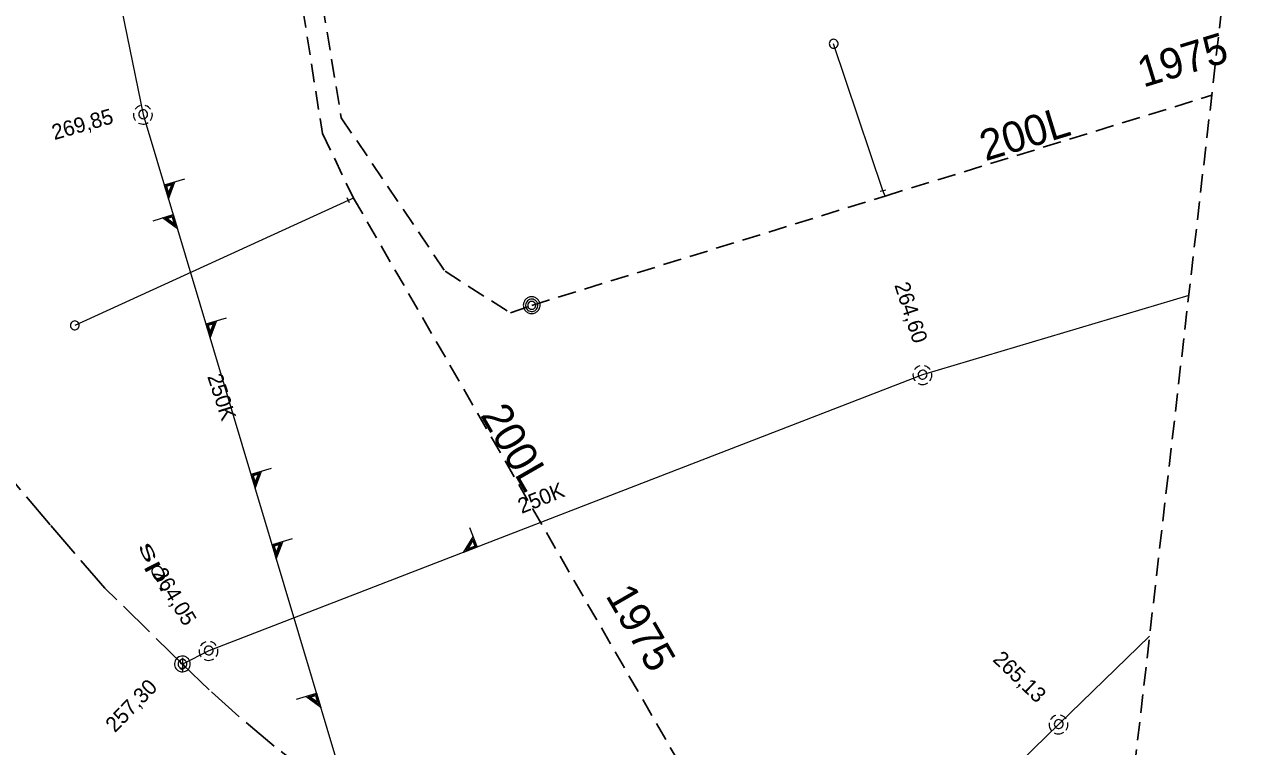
# Model space of a CAD drawing. Extents: x -743212 to -743020, y -1051380 to -1051228.
# Drawn here: x -743084.5 to -743020, y -1051298.4 to -1051260.7 of the extents above; entities that cross this region are included whole.
import ezdxf

# ---------------------------------------------------------------- set-up
doc = ezdxf.new("R2010")
doc.units = 0
doc.header["$LTSCALE"] = 0.32
doc.linetypes.add('LONG_DASHED', pattern=[7.5, 6, -1.5])
doc.linetypes.add('MEDIUM_DASHED', pattern=[4.5, 3, -1.5])
for name, color, linetype, lineweight in [('1', 7, 'MEDIUM_DASHED', 25), ('18', 7, 'Continuous', 13), ('20', 7, 'Continuous', 13), ('8', 7, 'Continuous', 13)]:
    doc.layers.add(name, color=color, linetype=linetype, lineweight=lineweight)

msp = doc.modelspace()

# ---------------------------------------------------------------- linework, layer by layer
at = {"layer": '1'}
msp.add_lwpolyline([(-743194.153, -1051227.724), (-743020.025, -1051242.759), (-743020.023, -1051242.759), (-743020.021, -1051242.76), (-743020.02, -1051242.761), (-743020.018, -1051242.762), (-743020.017, -1051242.764), (-743020.016, -1051242.766), (-743020.016, -1051242.768), (-743020.016, -1051242.77), (-743035.817, -1051380.315), (-743035.817, -1051380.317), (-743035.818, -1051380.318), (-743035.819, -1051380.32), (-743035.82, -1051380.321), (-743035.822, -1051380.322), (-743035.824, -1051380.323), (-743035.826, -1051380.323), (-743035.828, -1051380.323), (-743211.786, -1051358.847)], dxfattribs=at)
at = {"layer": '18'}
msp.add_line((-743076.25, -1051293.783), (-743076.25, -1051294.471), dxfattribs=at)
for points in [[(-743078.453, -1051264.936), (-743078.524, -1051264.964), (-743078.591, -1051265.003), (-743078.651, -1051265.051), (-743078.702, -1051265.108), (-743078.726, -1051265.142)], [(-743077.912, -1051265.119), (-743077.962, -1051265.061), (-743078.02, -1051265.011), (-743078.085, -1051264.97), (-743078.156, -1051264.941), (-743078.205, -1051264.927)], [(-743078.798, -1051265.328), (-743078.804, -1051265.405), (-743078.799, -1051265.482), (-743078.782, -1051265.557), (-743078.753, -1051265.628), (-743078.713, -1051265.694), (-743078.697, -1051265.716)], [(-743077.917, -1051265.705), (-743077.876, -1051265.64), (-743077.845, -1051265.57), (-743077.826, -1051265.495), (-743077.818, -1051265.419), (-743077.823, -1051265.342), (-743077.829, -1051265.307)], [(-743078.54, -1051265.845), (-743078.47, -1051265.876), (-743078.395, -1051265.895), (-743078.319, -1051265.902), (-743078.242, -1051265.897), (-743078.167, -1051265.88), (-743078.095, -1051265.852), (-743078.035, -1051265.817)], [(-743076.148, -1051268.771), (-743077.198, -1051269.085), (-743076.977, -1051269.824), (-743076.644, -1051268.919)], [(-743076.742, -1051269.002), (-743077.141, -1051269.121), (-743076.979, -1051269.663), (-743076.741, -1051269.002)], [(-743076.809, -1051269.071), (-743077.088, -1051269.155), (-743076.982, -1051269.51), (-743076.81, -1051269.07)], [(-743077.782, -1051270.946), (-743076.732, -1051270.631), (-743076.511, -1051271.369), (-743077.286, -1051270.797)], [(-743077.158, -1051270.811), (-743076.76, -1051270.692), (-743076.597, -1051271.234), (-743077.159, -1051270.812)], [(-743077.064, -1051270.832), (-743076.786, -1051270.749), (-743076.679, -1051271.105), (-743077.065, -1051270.831)], [(-743073.972, -1051276.038), (-743075.022, -1051276.352), (-743074.801, -1051277.091), (-743074.468, -1051276.186)], [(-743074.566, -1051276.269), (-743074.965, -1051276.388), (-743074.803, -1051276.93), (-743074.565, -1051276.269)], [(-743074.633, -1051276.338), (-743074.912, -1051276.422), (-743074.806, -1051276.777), (-743074.634, -1051276.337)], [(-743038.097, -1051278.928), (-743038.103, -1051279.005), (-743038.098, -1051279.082), (-743038.081, -1051279.157), (-743038.052, -1051279.228), (-743038.012, -1051279.294), (-743037.996, -1051279.316)], [(-743037.752, -1051278.536), (-743037.823, -1051278.564), (-743037.89, -1051278.603), (-743037.95, -1051278.651), (-743038.001, -1051278.708), (-743038.025, -1051278.742)], [(-743037.211, -1051278.719), (-743037.261, -1051278.661), (-743037.319, -1051278.611), (-743037.384, -1051278.57), (-743037.455, -1051278.541), (-743037.504, -1051278.527)], [(-743037.216, -1051279.305), (-743037.175, -1051279.24), (-743037.144, -1051279.17), (-743037.125, -1051279.095), (-743037.117, -1051279.019), (-743037.122, -1051278.942), (-743037.128, -1051278.907)], [(-743037.839, -1051279.445), (-743037.769, -1051279.476), (-743037.694, -1051279.495), (-743037.618, -1051279.502), (-743037.541, -1051279.497), (-743037.466, -1051279.48), (-743037.394, -1051279.452), (-743037.334, -1051279.417)], [(-743071.622, -1051283.886), (-743072.672, -1051284.2), (-743072.451, -1051284.939), (-743072.118, -1051284.034)], [(-743072.216, -1051284.117), (-743072.615, -1051284.236), (-743072.453, -1051284.778), (-743072.215, -1051284.117)], [(-743072.283, -1051284.186), (-743072.562, -1051284.27), (-743072.456, -1051284.625), (-743072.284, -1051284.185)], [(-743061.258, -1051286.97), (-743060.863, -1051287.992), (-743061.582, -1051288.27), (-743061.072, -1051287.453)], [(-743070.519, -1051287.568), (-743071.569, -1051287.882), (-743071.348, -1051288.621), (-743071.015, -1051287.716)], [(-743071.113, -1051287.799), (-743071.512, -1051287.918), (-743071.35, -1051288.46), (-743071.112, -1051287.799)], [(-743071.18, -1051287.868), (-743071.459, -1051287.952), (-743071.353, -1051288.307), (-743071.181, -1051287.867)], [(-743061.076, -1051287.581), (-743060.926, -1051287.969), (-743061.454, -1051288.173), (-743061.076, -1051287.58)], [(-743061.089, -1051287.676), (-743060.984, -1051287.948), (-743061.331, -1051288.082), (-743061.088, -1051287.676)], [(-743075.377, -1051293.338), (-743075.382, -1051293.415), (-743075.377, -1051293.492), (-743075.36, -1051293.567), (-743075.331, -1051293.638), (-743075.291, -1051293.704), (-743075.276, -1051293.726)], [(-743075.032, -1051292.946), (-743075.103, -1051292.974), (-743075.169, -1051293.013), (-743075.23, -1051293.061), (-743075.281, -1051293.118), (-743075.304, -1051293.152)], [(-743074.49, -1051293.129), (-743074.541, -1051293.071), (-743074.598, -1051293.021), (-743074.664, -1051292.98), (-743074.735, -1051292.951), (-743074.784, -1051292.937)], [(-743074.495, -1051293.715), (-743074.455, -1051293.65), (-743074.424, -1051293.58), (-743074.404, -1051293.505), (-743074.397, -1051293.429), (-743074.402, -1051293.352), (-743074.407, -1051293.317)], [(-743076.126, -1051293.93), (-743076.146, -1051293.897), (-743076.175, -1051293.871), (-743076.211, -1051293.854), (-743076.251, -1051293.85), (-743076.289, -1051293.857), (-743076.324, -1051293.876), (-743076.352, -1051293.904), (-743076.37, -1051293.939), (-743076.376, -1051293.978), (-743076.371, -1051294.017), (-743076.354, -1051294.053), (-743076.327, -1051294.082), (-743076.293, -1051294.101), (-743076.255, -1051294.11)], [(-743075.119, -1051293.855), (-743075.049, -1051293.886), (-743074.973, -1051293.905), (-743074.897, -1051293.912), (-743074.821, -1051293.907), (-743074.745, -1051293.89), (-743074.674, -1051293.862), (-743074.614, -1051293.827)], [(-743076.385, -1051294.297), (-743076.363, -1051294.33), (-743076.332, -1051294.355), (-743076.295, -1051294.369), (-743076.256, -1051294.372), (-743076.217, -1051294.363), (-743076.183, -1051294.343), (-743076.157, -1051294.313), (-743076.14, -1051294.277), (-743076.135, -1051294.238), (-743076.142, -1051294.199), (-743076.16, -1051294.164), (-743076.188, -1051294.136), (-743076.223, -1051294.117), (-743076.255, -1051294.11)], [(-743070.296, -1051295.944), (-743069.246, -1051295.629), (-743069.025, -1051296.367), (-743069.8, -1051295.795)], [(-743069.672, -1051295.809), (-743069.274, -1051295.69), (-743069.111, -1051296.232), (-743069.673, -1051295.81)], [(-743069.578, -1051295.83), (-743069.3, -1051295.747), (-743069.193, -1051296.103), (-743069.579, -1051295.829)], [(-743030.988, -1051297.181), (-743030.994, -1051297.258), (-743030.989, -1051297.335), (-743030.972, -1051297.41), (-743030.943, -1051297.481), (-743030.902, -1051297.547), (-743030.887, -1051297.569)], [(-743030.643, -1051296.789), (-743030.714, -1051296.817), (-743030.781, -1051296.856), (-743030.841, -1051296.904), (-743030.892, -1051296.961), (-743030.916, -1051296.995)], [(-743030.102, -1051296.972), (-743030.152, -1051296.914), (-743030.21, -1051296.864), (-743030.275, -1051296.823), (-743030.346, -1051296.794), (-743030.395, -1051296.78)], [(-743030.107, -1051297.558), (-743030.066, -1051297.493), (-743030.035, -1051297.423), (-743030.016, -1051297.348), (-743030.008, -1051297.272), (-743030.013, -1051297.195), (-743030.019, -1051297.16)], [(-743030.73, -1051297.698), (-743030.66, -1051297.729), (-743030.585, -1051297.748), (-743030.509, -1051297.755), (-743030.432, -1051297.75), (-743030.357, -1051297.733), (-743030.285, -1051297.705), (-743030.225, -1051297.67)]]:
    msp.add_lwpolyline(points, dxfattribs=at)
for points in [[(-743078.069, -1051265.388), (-743078.075, -1051265.336), (-743078.093, -1051265.286), (-743078.121, -1051265.242), (-743078.159, -1051265.205), (-743078.204, -1051265.178), (-743078.254, -1051265.162), (-743078.306, -1051265.157), (-743078.358, -1051265.164), (-743078.407, -1051265.183), (-743078.451, -1051265.213), (-743078.486, -1051265.252), (-743078.512, -1051265.297), (-743078.527, -1051265.348), (-743078.53, -1051265.4), (-743078.522, -1051265.452), (-743078.501, -1051265.5), (-743078.471, -1051265.543), (-743078.431, -1051265.578), (-743078.385, -1051265.602), (-743078.334, -1051265.616), (-743078.282, -1051265.618), (-743078.23, -1051265.608), (-743078.182, -1051265.586), (-743078.14, -1051265.554), (-743078.107, -1051265.514), (-743078.083, -1051265.467), (-743078.071, -1051265.416)], [(-743037.368, -1051278.988), (-743037.374, -1051278.936), (-743037.392, -1051278.886), (-743037.42, -1051278.842), (-743037.458, -1051278.805), (-743037.503, -1051278.778), (-743037.553, -1051278.762), (-743037.605, -1051278.757), (-743037.657, -1051278.764), (-743037.706, -1051278.783), (-743037.75, -1051278.813), (-743037.785, -1051278.852), (-743037.811, -1051278.897), (-743037.826, -1051278.948), (-743037.829, -1051279), (-743037.821, -1051279.052), (-743037.8, -1051279.1), (-743037.77, -1051279.143), (-743037.73, -1051279.178), (-743037.684, -1051279.202), (-743037.633, -1051279.216), (-743037.581, -1051279.218), (-743037.529, -1051279.208), (-743037.481, -1051279.186), (-743037.439, -1051279.154), (-743037.406, -1051279.114), (-743037.382, -1051279.067), (-743037.37, -1051279.016)], [(-743074.647, -1051293.398), (-743074.654, -1051293.346), (-743074.671, -1051293.296), (-743074.7, -1051293.252), (-743074.738, -1051293.215), (-743074.782, -1051293.188), (-743074.833, -1051293.172), (-743074.885, -1051293.167), (-743074.936, -1051293.174), (-743074.985, -1051293.193), (-743075.029, -1051293.223), (-743075.065, -1051293.262), (-743075.091, -1051293.307), (-743075.105, -1051293.358), (-743075.108, -1051293.41), (-743075.1, -1051293.462), (-743075.08, -1051293.51), (-743075.049, -1051293.553), (-743075.01, -1051293.588), (-743074.963, -1051293.612), (-743074.913, -1051293.626), (-743074.86, -1051293.628), (-743074.809, -1051293.618), (-743074.761, -1051293.596), (-743074.718, -1051293.564), (-743074.686, -1051293.524), (-743074.662, -1051293.477), (-743074.649, -1051293.426)], [(-743075.84, -1051294.1), (-743075.846, -1051294.03), (-743075.864, -1051293.963), (-743075.893, -1051293.899), (-743075.933, -1051293.841), (-743075.982, -1051293.79), (-743076.038, -1051293.749), (-743076.101, -1051293.717), (-743076.168, -1051293.697), (-743076.238, -1051293.689), (-743076.308, -1051293.692), (-743076.377, -1051293.708), (-743076.442, -1051293.735), (-743076.501, -1051293.772), (-743076.553, -1051293.819), (-743076.597, -1051293.875), (-743076.63, -1051293.936), (-743076.652, -1051294.003), (-743076.663, -1051294.072), (-743076.662, -1051294.143), (-743076.649, -1051294.212), (-743076.624, -1051294.277), (-743076.588, -1051294.338), (-743076.543, -1051294.392), (-743076.489, -1051294.437), (-743076.429, -1051294.472), (-743076.363, -1051294.497), (-743076.294, -1051294.51), (-743076.224, -1051294.511), (-743076.154, -1051294.5), (-743076.088, -1051294.478), (-743076.026, -1051294.445), (-743075.971, -1051294.401), (-743075.924, -1051294.349), (-743075.886, -1051294.29), (-743075.86, -1051294.225), (-743075.844, -1051294.156)], [(-743076.019, -1051294.099), (-743076.025, -1051294.047), (-743076.043, -1051293.997), (-743076.071, -1051293.953), (-743076.109, -1051293.916), (-743076.154, -1051293.889), (-743076.204, -1051293.873), (-743076.256, -1051293.868), (-743076.308, -1051293.875), (-743076.357, -1051293.894), (-743076.401, -1051293.924), (-743076.436, -1051293.963), (-743076.462, -1051294.008), (-743076.477, -1051294.059), (-743076.48, -1051294.111), (-743076.472, -1051294.163), (-743076.451, -1051294.211), (-743076.421, -1051294.254), (-743076.381, -1051294.289), (-743076.335, -1051294.313), (-743076.284, -1051294.327), (-743076.232, -1051294.329), (-743076.18, -1051294.319), (-743076.132, -1051294.297), (-743076.09, -1051294.265), (-743076.057, -1051294.225), (-743076.033, -1051294.178), (-743076.021, -1051294.127)], [(-743030.259, -1051297.241), (-743030.265, -1051297.189), (-743030.282, -1051297.139), (-743030.311, -1051297.095), (-743030.349, -1051297.058), (-743030.394, -1051297.031), (-743030.444, -1051297.015), (-743030.496, -1051297.01), (-743030.548, -1051297.017), (-743030.597, -1051297.036), (-743030.641, -1051297.066), (-743030.676, -1051297.105), (-743030.702, -1051297.15), (-743030.717, -1051297.201), (-743030.72, -1051297.253), (-743030.712, -1051297.305), (-743030.691, -1051297.353), (-743030.661, -1051297.396), (-743030.621, -1051297.431), (-743030.575, -1051297.455), (-743030.524, -1051297.469), (-743030.472, -1051297.471), (-743030.42, -1051297.461), (-743030.372, -1051297.439), (-743030.33, -1051297.407), (-743030.297, -1051297.367), (-743030.273, -1051297.32), (-743030.261, -1051297.269)]]:
    msp.add_lwpolyline(points, close=True, dxfattribs=at)
at = {"layer": '20'}
for p, q in [((-743084.112, -1051237.225), (-743078.3, -1051265.399)), ((-743084.112, -1051237.225), (-743078.3, -1051265.399)), ((-743078.3, -1051265.399), (-743067.1, -1051302.8)), ((-743078.3, -1051265.399), (-743067.1, -1051302.8)), ((-743023.701, -1051274.85), (-743037.599, -1051278.999)), ((-743023.701, -1051274.85), (-743037.599, -1051278.999)), ((-743037.599, -1051278.999), (-743074.879, -1051293.409)), ((-743037.599, -1051278.999), (-743074.879, -1051293.409)), ((-743025.745, -1051292.642), (-743030.49, -1051297.252)), ((-743025.745, -1051292.642), (-743030.49, -1051297.252)), ((-743074.879, -1051293.409), (-743076.25, -1051294.11)), ((-743074.879, -1051293.409), (-743076.25, -1051294.11)), ((-743030.49, -1051297.252), (-743053.699, -1051319.8)), ((-743030.49, -1051297.252), (-743053.699, -1051319.8))]:
    msp.add_line(p, q, dxfattribs=at)
at = {"layer": '20', "linetype": 'LONG_DASHED', "lineweight": 25}
for points in [[(-743076.25, -1051294.11), (-743080.298, -1051290.141), (-743083.155, -1051286.838), (-743088, -1051281.159)], [(-743076.25, -1051294.11), (-743080.298, -1051290.141), (-743083.155, -1051286.838), (-743088, -1051281.159)], [(-743069.586, -1051299.847), (-743071.454, -1051298.396), (-743073.302, -1051296.848), (-743074.85, -1051295.453), (-743076.25, -1051294.11)], [(-743069.586, -1051299.847), (-743071.454, -1051298.396), (-743073.302, -1051296.848), (-743074.85, -1051295.453), (-743076.25, -1051294.11)]]:
    msp.add_lwpolyline(points, dxfattribs=at)
at = {"layer": '8'}
for p, q in [((-743039.67, -1051269.37), (-743042.247, -1051261.713)), ((-743039.81, -1051269.407), (-743039.516, -1051269.329)), ((-743039.559, -1051269.659), (-743039.67, -1051269.37)), ((-743067.59, -1051269.889), (-743081.866, -1051276.423)), ((-743067.528, -1051270.021), (-743067.654, -1051269.744)), ((-743067.317, -1051269.764), (-743067.59, -1051269.889))]:
    msp.add_line(p, q, dxfattribs=at)
at = {"layer": '8', "linetype": 'MEDIUM_DASHED', "lineweight": 25}
for points in [[(-743072.836, -1051238.199), (-743072.636, -1051242.843), (-743068.943, -1051266.389), (-743067.317, -1051269.764), (-743041.789, -1051314.04)], [(-743071.973, -1051238.273), (-743071.77, -1051242.625), (-743067.953, -1051265.57), (-743062.537, -1051273.588), (-743059.127, -1051275.767), (-743058.006, -1051275.37)], [(-743058.006, -1051275.37), (-743039.559, -1051269.659), (-743022.5, -1051264.397)]]:
    msp.add_lwpolyline(points, dxfattribs=at)
at = {"layer": '8'}
for points in [[(-743042.023, -1051261.772), (-743042.013, -1051261.721), (-743042.015, -1051261.668), (-743042.029, -1051261.618), (-743042.054, -1051261.571), (-743042.088, -1051261.531), (-743042.131, -1051261.501), (-743042.179, -1051261.481), (-743042.231, -1051261.471), (-743042.283, -1051261.475), (-743042.334, -1051261.49), (-743042.379, -1051261.517), (-743042.418, -1051261.552), (-743042.448, -1051261.596), (-743042.466, -1051261.644), (-743042.474, -1051261.696), (-743042.469, -1051261.748), (-743042.453, -1051261.798), (-743042.426, -1051261.844), (-743042.389, -1051261.881), (-743042.345, -1051261.91), (-743042.296, -1051261.927), (-743042.243, -1051261.933), (-743042.191, -1051261.927), (-743042.141, -1051261.909), (-743042.098, -1051261.881), (-743042.06, -1051261.843), (-743042.034, -1051261.798)], [(-743057.689, -1051275.367), (-743057.695, -1051275.306), (-743057.713, -1051275.246), (-743057.742, -1051275.191), (-743057.781, -1051275.143), (-743057.828, -1051275.103), (-743057.882, -1051275.073), (-743057.941, -1051275.053), (-743058.003, -1051275.046), (-743058.065, -1051275.05), (-743058.125, -1051275.066), (-743058.18, -1051275.094), (-743058.23, -1051275.131), (-743058.271, -1051275.178), (-743058.303, -1051275.231), (-743058.323, -1051275.29), (-743058.333, -1051275.351), (-743058.33, -1051275.413), (-743058.315, -1051275.473), (-743058.289, -1051275.53), (-743058.253, -1051275.58), (-743058.207, -1051275.623), (-743058.155, -1051275.655), (-743058.097, -1051275.678), (-743058.036, -1051275.688), (-743057.974, -1051275.687), (-743057.913, -1051275.674), (-743057.856, -1051275.649), (-743057.805, -1051275.614), (-743057.761, -1051275.57), (-743057.727, -1051275.518), (-743057.703, -1051275.461), (-743057.691, -1051275.4)], [(-743057.803, -1051275.367), (-743057.809, -1051275.318), (-743057.826, -1051275.271), (-743057.854, -1051275.23), (-743057.892, -1051275.197), (-743057.936, -1051275.173), (-743057.984, -1051275.161), (-743058.034, -1051275.16), (-743058.082, -1051275.172), (-743058.127, -1051275.194), (-743058.165, -1051275.227), (-743058.194, -1051275.267), (-743058.213, -1051275.314), (-743058.22, -1051275.363), (-743058.215, -1051275.413), (-743058.198, -1051275.46), (-743058.171, -1051275.502), (-743058.134, -1051275.536), (-743058.091, -1051275.56), (-743058.043, -1051275.574), (-743057.993, -1051275.575), (-743057.944, -1051275.565), (-743057.899, -1051275.543), (-743057.86, -1051275.511), (-743057.83, -1051275.472), (-743057.811, -1051275.426), (-743057.803, -1051275.376)], [(-743081.66, -1051276.317), (-743081.687, -1051276.272), (-743081.724, -1051276.234), (-743081.768, -1051276.206), (-743081.818, -1051276.188), (-743081.87, -1051276.182), (-743081.922, -1051276.188), (-743081.971, -1051276.205), (-743082.016, -1051276.233), (-743082.052, -1051276.271), (-743082.08, -1051276.317), (-743082.096, -1051276.367), (-743082.101, -1051276.418), (-743082.093, -1051276.471), (-743082.074, -1051276.52), (-743082.045, -1051276.564), (-743082.006, -1051276.598), (-743081.961, -1051276.625), (-743081.91, -1051276.64), (-743081.858, -1051276.643), (-743081.806, -1051276.634), (-743081.758, -1051276.615), (-743081.715, -1051276.584), (-743081.68, -1051276.544), (-743081.655, -1051276.497), (-743081.642, -1051276.447), (-743081.64, -1051276.394), (-743081.65, -1051276.343)]]:
    msp.add_lwpolyline(points, close=True, dxfattribs=at)
msp.add_lwpolyline([(-743057.576, -1051275.359), (-743057.578, -1051275.314), (-743057.585, -1051275.269), (-743057.597, -1051275.224), (-743057.613, -1051275.182), (-743057.634, -1051275.141), (-743057.659, -1051275.102), (-743057.688, -1051275.067), (-743057.72, -1051275.034), (-743057.756, -1051275.006), (-743057.794, -1051274.981), (-743057.835, -1051274.96), (-743057.878, -1051274.943), (-743057.922, -1051274.931), (-743057.967, -1051274.924), (-743058.013, -1051274.922), (-743058.059, -1051274.924), (-743058.104, -1051274.931), (-743058.148, -1051274.943), (-743058.191, -1051274.96), (-743058.232, -1051274.981), (-743058.27, -1051275.006), (-743058.306, -1051275.034), (-743058.338, -1051275.067), (-743058.367, -1051275.102), (-743058.392, -1051275.141), (-743058.413, -1051275.182), (-743058.429, -1051275.224), (-743058.441, -1051275.269), (-743058.448, -1051275.314), (-743058.451, -1051275.36), (-743058.448, -1051275.405), (-743058.441, -1051275.45), (-743058.429, -1051275.495), (-743058.413, -1051275.537), (-743058.392, -1051275.578), (-743058.367, -1051275.617), (-743058.338, -1051275.652), (-743058.306, -1051275.685), (-743058.27, -1051275.713), (-743058.232, -1051275.738), (-743058.191, -1051275.759), (-743058.148, -1051275.776), (-743058.104, -1051275.787), (-743058.059, -1051275.795), (-743058.013, -1051275.797), (-743057.967, -1051275.795), (-743057.922, -1051275.787), (-743057.878, -1051275.776), (-743057.835, -1051275.759), (-743057.794, -1051275.738), (-743057.756, -1051275.713), (-743057.72, -1051275.685), (-743057.688, -1051275.652), (-743057.659, -1051275.617), (-743057.634, -1051275.578), (-743057.613, -1051275.537), (-743057.597, -1051275.495), (-743057.585, -1051275.45), (-743057.578, -1051275.405), (-743057.576, -1051275.36)], dxfattribs=at)

# ---------------------------------------------------------------- texts
at = {"layer": '1'}
for s, height, rotation, p in [('1975', 1.6, 17, (-743026.075, -1051263.999)), ('269,85', 0.8, 16, (-743082.94, -1051266.738)), ('200L', 1.6, 17, (-743034.314, -1051267.843)), ('264,60', 0.8, 288, (-743039.084, -1051274.304)), ('250K', 0.8, 288, (-743074.96, -1051279.082)), ('200L', 1.6, 300, (-743060.722, -1051281.097)), ('250K', 0.8, 22, (-743058.537, -1051286.265)), ('264,05', 0.8, 301, (-743077.838, -1051289.375)), ('1975', 1.6, 300, (-743054.181, -1051290.528)), ('265,13', 0.8, 316, (-743033.981, -1051293.914)), ('257,30', 0.8, 46, (-743079.776, -1051297.725))]:
    msp.add_text(s, height=height, rotation=rotation, dxfattribs=at).set_placement(p)
at = {"layer": '1', "width": 2}
msp.add_text('sp. ', height=0.8, rotation=297, dxfattribs=at).set_placement((-743078.579, -1051287.947))

doc.saveas('drawing.dxf')
